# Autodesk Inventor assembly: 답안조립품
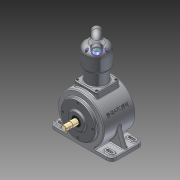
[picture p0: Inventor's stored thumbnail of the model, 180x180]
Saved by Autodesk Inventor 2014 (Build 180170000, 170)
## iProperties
Created: 2015-06
Part Number: 답안조립품
Document SubType Name: Assembly
Designer: basic
Author: basic
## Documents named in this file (15)
- C:\Users\basic\Desktop\450605V1023\답안조립품.iam
- C:\Users\basic\Desktop\450605V1023\본체.ipt
- C:\Users\basic\Desktop\450605V1023\M4x0.7.ipt
- C:\Users\basic\Desktop\450605V1023\M5x0.8.ipt
- C:\Users\basic\Desktop\450605V1023\메인 크랭크 축-구동부.ipt
- C:\Users\basic\Desktop\450605V1023\메인커버.ipt
- C:\Users\basic\Desktop\450605V1023\베어링 6204.ipt
- C:\Users\basic\Desktop\450605V1023\베어링 NA 4902.ipt
- C:\Users\basic\Desktop\450605V1023\실린더.ipt
- C:\Users\basic\Desktop\450605V1023\실린더헤드.ipt
- C:\Users\basic\Desktop\450605V1023\오일실.ipt
- C:\Users\basic\Desktop\450605V1023\커넥팅 로드.ipt
- C:\Users\basic\Desktop\450605V1023\크랭크 서브축.ipt
- C:\Users\basic\Desktop\450605V1023\피스톤 핀.ipt
- C:\Users\basic\Desktop\450605V1023\피스톤.ipt
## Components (14 placed, 4 different names)
1. 피스톤 핀:1
2. 피스톤:1
3. M4x0.7:2
4. M4x0.7:3
5. M4x0.7:4
6. M4x0.7:5
7. M4x0.7:1
8. M4x0.7:6
9. M4x0.7:7
10. M4x0.7:8
11. M5x0.8:1
12. M5x0.8:2
13. M5x0.8:3
14. M5x0.8:4
